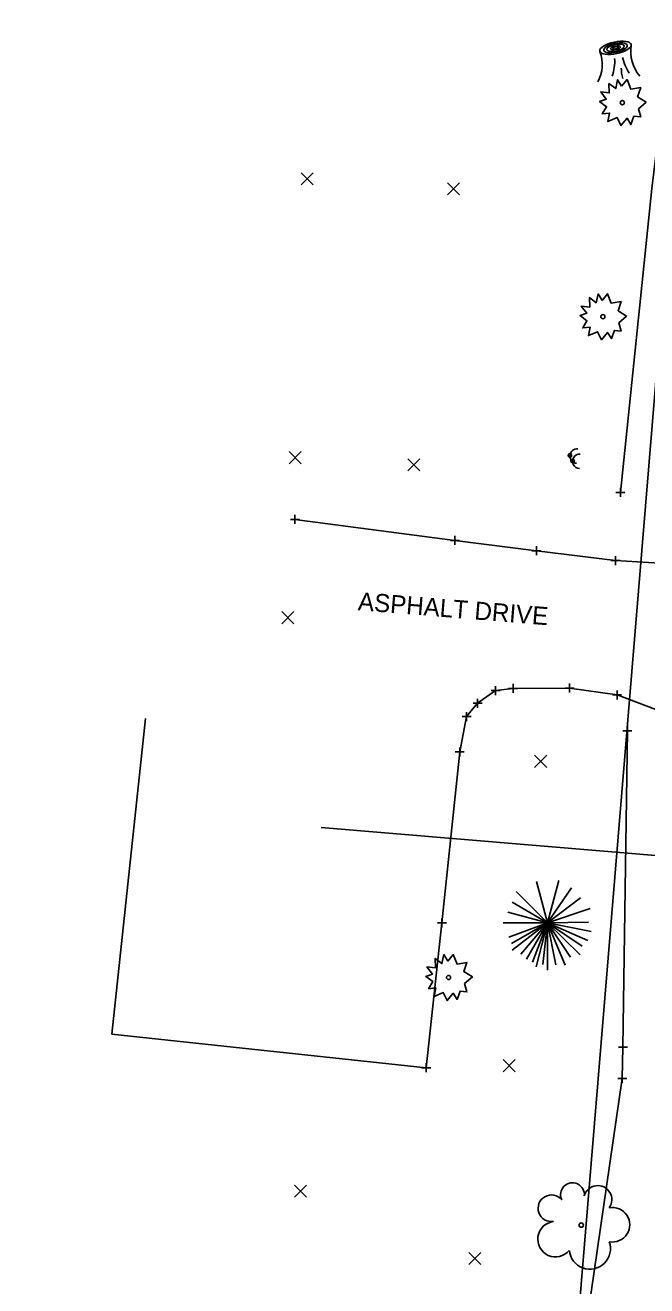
# Model space of a CAD drawing. Extents: x 1380440 to 1381945, y 468756 to 470369.
# Drawn here: x 1381439.7 to 1381508.5, y 469112.5 to 469252.2 of the extents above; entities that cross this region are included whole.
import ezdxf

# ---------------------------------------------------------------- set-up
doc = ezdxf.new("R2010")
doc.units = 0
for name, color, linetype in [('GE_P_Driveway_CL', 7, 'Continuous'), ('PV_X_COP', 7, 'Continuous'), ('RW_X_Esmt_SH', 7, 'Continuous'), ('SC_Scratch10', 7, 'Continuous'), ('SC_Scratch2', 7, 'Continuous'), ('SH_Named_Boundary', 7, 'Continuous'), ('UT_X_Gas', 7, 'Continuous'), ('UT_X_Water', 7, 'Continuous'), ('X-SUBDIVISION', 7, 'Continuous')]:
    doc.layers.add(name, color=color, linetype=linetype)

msp = doc.modelspace()

# ---------------------------------------------------------------- linework, layer by layer
at = {"layer": 'GE_P_Driveway_CL'}
for p, q in [((1381470.26, 469234.47), (1381471.59, 469235.81)), ((1381470.26, 469235.81), (1381471.59, 469234.47)), ((1381486.47, 469233.38), (1381487.8, 469234.71)), ((1381486.47, 469234.71), (1381487.8, 469233.38)), ((1381468.93, 469203.59), (1381470.26, 469204.93)), ((1381468.93, 469204.93), (1381470.26, 469203.59)), ((1381482.07, 469202.79), (1381483.4, 469204.12)), ((1381482.07, 469204.12), (1381483.4, 469202.79)), ((1381468.12, 469185.87), (1381469.46, 469187.21)), ((1381468.12, 469187.21), (1381469.46, 469185.87)), ((1381496.12, 469169.95), (1381497.46, 469171.29)), ((1381496.12, 469171.29), (1381497.46, 469169.95)), ((1381492.65, 469136.24), (1381493.98, 469137.58)), ((1381492.65, 469137.58), (1381493.98, 469136.24)), ((1381469.53, 469122.33), (1381470.86, 469123.66)), ((1381469.53, 469123.66), (1381470.86, 469122.33)), ((1381488.83, 469114.89), (1381490.16, 469116.22)), ((1381488.83, 469116.22), (1381490.16, 469114.89))]:
    msp.add_line(p, q, dxfattribs=at)
at = {"layer": 'PV_X_COP'}
for centre in [(1381500.03, 469204.5), (1381500.32, 469203.9)]:
    msp.add_circle(centre, 0.2, dxfattribs=at)
for centre, start, end in [((1381500.83, 469204.43), 84.7522, 264.7522), ((1381501.12, 469203.85), 86.9506, 266.9506)]:
    msp.add_arc(centre, 0.8, start, end, dxfattribs=at)
at = {"layer": 'RW_X_Esmt_SH'}
for p, q in [((1381449.3, 469140.39), (1381453.02, 469175.37)), ((1381484.11, 469136.69), (1381449.3, 469140.39))]:
    msp.add_line(p, q, dxfattribs=at)
for points in [[(1381522.81, 469196), (1381520.24, 469194.81), (1381517.53, 469193.38), (1381515.86, 469192.8), (1381513.44, 469192.4), (1381511.17, 469192.5), (1381505.08, 469192.85), (1381496.32, 469193.94), (1381487.29, 469195.09), (1381469.58, 469197.42)], [(1381487.83, 469171.67), (1381488.59, 469175.57), (1381489.8, 469177.06), (1381491.8, 469178.46), (1381493.74, 469178.7), (1381500, 469178.74), (1381505.25, 469177.97), (1381510.63, 469175.94), (1381513.75, 469175.08), (1381519.99, 469168.46), (1381519.16, 469158.01), (1381519.54, 469157.13)], [(1381487.83, 469171.67), (1381485.85, 469152.72), (1381484.11, 469136.69)]]:
    msp.add_lwpolyline(points, dxfattribs=at)
at = {"layer": 'SC_Scratch10'}
for p, q in [((1381505.45, 469248.14), (1381505.45, 469248.14)), ((1381497.56, 469152.72), (1381496.32, 469157.33)), ((1381497.56, 469152.72), (1381498.81, 469157.41)), ((1381497.56, 469152.72), (1381494.07, 469156.2)), ((1381497.56, 469152.72), (1381500.21, 469156.6)), ((1381497.56, 469152.72), (1381493.65, 469155.01)), ((1381497.56, 469152.72), (1381501.21, 469155.52)), ((1381497.56, 469152.72), (1381502.29, 469154.32)), ((1381497.56, 469152.72), (1381493.14, 469153.9)), ((1381492.62, 469152.72), (1381497.56, 469152.72)), ((1381497.56, 469152.72), (1381493.27, 469151.15)), ((1381497.56, 469152.72), (1381493.57, 469150.43)), ((1381497.56, 469152.72), (1381493.65, 469149.72)), ((1381497.56, 469152.72), (1381494.61, 469149.25)), ((1381497.56, 469152.72), (1381495.24, 469148.7)), ((1381497.56, 469152.72), (1381495.89, 469148.38)), ((1381497.56, 469152.72), (1381496.29, 469147.86)), ((1381497.56, 469152.72), (1381497.02, 469148.12)), ((1381497.56, 469152.72), (1381502.07, 469152.81)), ((1381497.56, 469147.48), (1381497.56, 469152.72)), ((1381497.56, 469152.72), (1381498.48, 469148.08)), ((1381497.56, 469152.72), (1381499.49, 469148.05)), ((1381497.56, 469152.72), (1381500.09, 469148.92)), ((1381497.56, 469152.72), (1381501.15, 469149.19)), ((1381497.56, 469152.72), (1381501.38, 469150.16)), ((1381497.56, 469152.72), (1381502.02, 469150.77)), ((1381497.56, 469152.72), (1381502.39, 469151.76))]:
    msp.add_line(p, q, dxfattribs=at)
for points in [[(1381505.75, 469245.39), (1381506.36, 469246.13), (1381506.77, 469245.07), (1381507.87, 469245.25), (1381507.53, 469244.24), (1381508.47, 469243.65), (1381507.62, 469242.91), (1381507.87, 469242), (1381507.11, 469242.07), (1381506.79, 469241.15), (1381506.36, 469241.85), (1381505.68, 469241.03), (1381505.25, 469241.92), (1381504.23, 469241.49), (1381504.43, 469242.43), (1381503.61, 469242.34), (1381504.09, 469243.13), (1381503.32, 469243.7), (1381504.06, 469243.97), (1381503.45, 469244.77), (1381504.38, 469244.66), (1381504.35, 469245.7), (1381505.1, 469245.13), (1381505.31, 469246.11), (1381505.75, 469245.39)], [(1381503.59, 469221.68), (1381504.2, 469222.41), (1381504.61, 469221.36), (1381505.7, 469221.54), (1381505.37, 469220.53), (1381506.31, 469219.93), (1381505.45, 469219.2), (1381505.7, 469218.28), (1381504.95, 469218.35), (1381504.63, 469217.44), (1381504.2, 469218.13), (1381503.52, 469217.31), (1381503.09, 469218.2), (1381502.07, 469217.77), (1381502.26, 469218.71), (1381501.45, 469218.63), (1381501.92, 469219.42), (1381501.16, 469219.99), (1381501.89, 469220.25), (1381501.29, 469221.05), (1381502.22, 469220.94), (1381502.19, 469221.98), (1381502.94, 469221.41), (1381503.15, 469222.4), (1381503.59, 469221.68)], [(1381486.51, 469148.49), (1381487.11, 469149.22), (1381487.53, 469148.17), (1381488.62, 469148.35), (1381488.28, 469147.34), (1381489.23, 469146.74), (1381488.37, 469146.01), (1381488.62, 469145.09), (1381487.87, 469145.16), (1381487.54, 469144.25), (1381487.11, 469144.94), (1381486.44, 469144.12), (1381486.01, 469145.01), (1381484.99, 469144.58), (1381485.18, 469145.52), (1381484.37, 469145.44), (1381484.84, 469146.23), (1381484.07, 469146.8), (1381484.81, 469147.06), (1381484.2, 469147.86), (1381485.14, 469147.75), (1381485.11, 469148.79), (1381485.86, 469148.22), (1381486.07, 469149.21), (1381486.51, 469148.49)]]:
    msp.add_lwpolyline(points, dxfattribs=at)
for centre, radius in [((1381505.84, 469243.58), 0.23), ((1381503.68, 469219.87), 0.23), ((1381486.59, 469146.68), 0.23), ((1381501.29, 469119.25), 0.24)]:
    msp.add_circle(centre, radius, dxfattribs=at)
for centre, radius, start, end in [((1381499.62, 469247.8), 4, 331.5338, 20.9269), ((1381511.06, 469249.28), 4.29, 171.4106, 219.9194), ((1381499.94, 469248.17), 5.05, 340.7938, 3.5481), ((1381511.96, 469250.2), 6.32, 194.9653, 212.1216), ((1381509.36, 469247.34), 3.64, 178.7926, 197.1224), ((1381500.31, 469122.62), 1.32, 354.0047, 205.9741), ((1381503.12, 469122.08), 1.55, 323.83, 165.0376), ((1381497.98, 469121.12), 1.47, 39.0625, 279.5412), ((1381504.75, 469119.29), 1.91, 259.1453, 101.4596), ((1381498.44, 469117.7), 1.97, 96.1722, 320.5737), ((1381502.24, 469116.65), 2.28, 184.9476, 19.4572)]:
    msp.add_arc(centre, radius, start, end, dxfattribs=at)
for major_axis in [(1.74, 0.37), (1.3, 0.28), (0.976, 0.211), (0.549, 0.119), (0.309, 0.067)]:
    msp.add_ellipse((1381505.08, 469249.65), major_axis=major_axis, ratio=0.36865, dxfattribs=at)
at = {"layer": 'SC_Scratch2'}
for points in [[(1381512.83, 469264.6), (1381509.11, 469234.08), (1381505.62, 469200.41)], [(1381506.4, 469174), (1381505.9, 469138.98), (1381505.83, 469135.51), (1381502.06, 469109.54)]]:
    msp.add_lwpolyline(points, dxfattribs=at)
at = {"layer": 'SH_Named_Boundary'}
for p, q in [((1381505.12, 469200.41), (1381506.12, 469200.41)), ((1381505.62, 469200.91), (1381505.62, 469199.91)), ((1381505.62, 469200.41), (1381505.62, 469200.41)), ((1381469.58, 469197.92), (1381469.58, 469196.92)), ((1381469.08, 469197.42), (1381470.08, 469197.42)), ((1381469.58, 469197.42), (1381469.58, 469197.42)), ((1381486.79, 469195.09), (1381487.79, 469195.09)), ((1381487.29, 469195.59), (1381487.29, 469194.59)), ((1381487.29, 469195.09), (1381487.29, 469195.09)), ((1381495.82, 469193.94), (1381496.82, 469193.94)), ((1381496.32, 469194.44), (1381496.32, 469193.44)), ((1381496.32, 469193.94), (1381496.32, 469193.94)), ((1381504.58, 469192.85), (1381505.58, 469192.85)), ((1381505.08, 469193.35), (1381505.08, 469192.35)), ((1381505.08, 469192.85), (1381505.08, 469192.85)), ((1381491.3, 469178.46), (1381492.3, 469178.46)), ((1381491.8, 469178.96), (1381491.8, 469177.96)), ((1381491.8, 469178.46), (1381491.8, 469178.46)), ((1381493.24, 469178.7), (1381494.24, 469178.7)), ((1381493.74, 469179.2), (1381493.74, 469178.2)), ((1381493.74, 469178.7), (1381493.74, 469178.7)), ((1381499.5, 469178.74), (1381500.5, 469178.74)), ((1381500, 469179.24), (1381500, 469178.24)), ((1381500, 469178.74), (1381500, 469178.74)), ((1381505.25, 469178.47), (1381505.25, 469177.47)), ((1381489.3, 469177.06), (1381490.3, 469177.06)), ((1381489.8, 469177.56), (1381489.8, 469176.56)), ((1381489.8, 469177.06), (1381489.8, 469177.06)), ((1381504.75, 469177.97), (1381505.75, 469177.97)), ((1381505.25, 469177.97), (1381505.25, 469177.97)), ((1381488.09, 469175.57), (1381489.09, 469175.57)), ((1381488.59, 469176.07), (1381488.59, 469175.07)), ((1381488.59, 469175.57), (1381488.59, 469175.57)), ((1381505.9, 469174), (1381506.9, 469174)), ((1381506.4, 469174.5), (1381506.4, 469173.5)), ((1381506.4, 469174), (1381506.4, 469174)), ((1381487.33, 469171.67), (1381488.33, 469171.67)), ((1381487.33, 469171.67), (1381488.33, 469171.67)), ((1381487.83, 469172.17), (1381487.83, 469171.17)), ((1381487.83, 469172.17), (1381487.83, 469171.17)), ((1381487.83, 469171.67), (1381487.83, 469171.67)), ((1381487.83, 469171.67), (1381487.83, 469171.67)), ((1381485.85, 469153.22), (1381485.85, 469152.22)), ((1381485.35, 469152.72), (1381486.35, 469152.72)), ((1381485.85, 469152.72), (1381485.85, 469152.72)), ((1381505.4, 469138.98), (1381506.4, 469138.98)), ((1381505.9, 469139.48), (1381505.9, 469138.48)), ((1381505.9, 469138.98), (1381505.9, 469138.98)), ((1381483.61, 469136.69), (1381484.61, 469136.69)), ((1381484.11, 469137.19), (1381484.11, 469136.19)), ((1381484.11, 469136.69), (1381484.11, 469136.69)), ((1381505.33, 469135.51), (1381506.33, 469135.51)), ((1381505.83, 469136.01), (1381505.83, 469135.01)), ((1381505.83, 469135.51), (1381505.83, 469135.51))]:
    msp.add_line(p, q, dxfattribs=at)
at = {"layer": 'UT_X_Gas'}
msp.add_lwpolyline([(1381485.9, 468926.41), (1381594.27, 470237.89), (1380558, 470279.29)], dxfattribs=at)
at = {"layer": 'UT_X_Water'}
msp.add_line((1381542.21, 469157.44), (1381472.47, 469163.31), dxfattribs=at)

# ---------------------------------------------------------------- texts
at = {"layer": 'X-SUBDIVISION'}
msp.add_text('ASPHALT DRIVE', height=2, rotation=355.4428, dxfattribs=at).set_placement((1381476.51, 469187.37))

doc.saveas('drawing.dxf')
